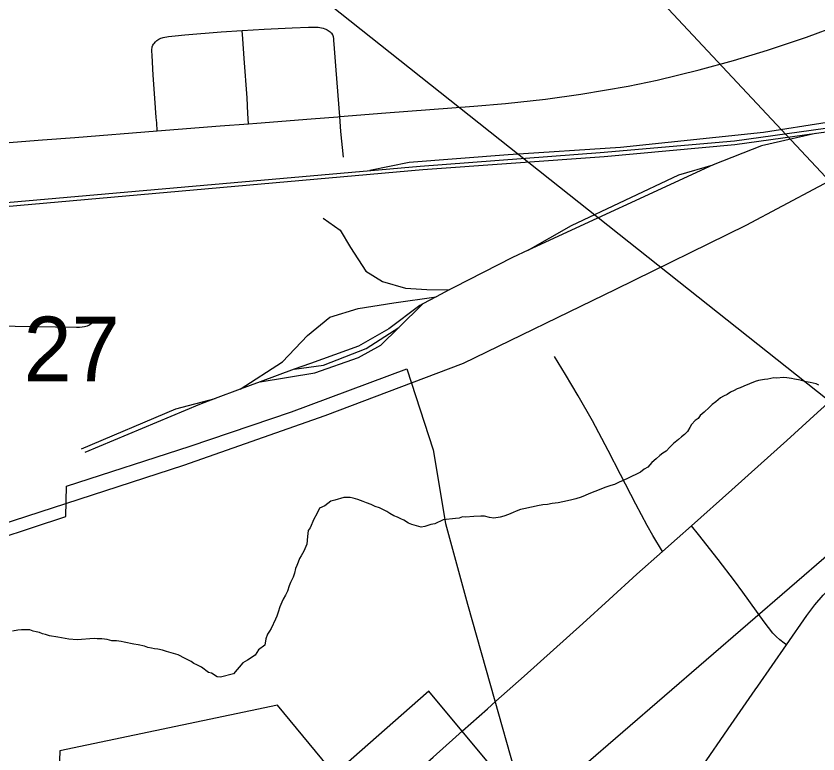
# Model space of a CAD drawing. Extents: x 0 to 34, y 0 to 22.
# Drawn here: x 4.887 to 5.405, y 17.65 to 18.127 of the extents above; entities that cross this region are included whole.
import ezdxf

# ---------------------------------------------------------------- set-up
doc = ezdxf.new("R2010")
doc.units = 0
for name, color, linetype in [('Default', 7, 'Continuous'), ('GM_X_City_Street', 7, 'Continuous'), ('GM_X_County_Road', 7, 'Continuous'), ('GM_X_Minor_River', 7, 'Continuous'), ('GM_X_Rail_Line', 7, 'Continuous'), ('GM_X_Section_Text', 7, 'Continuous'), ('GM_X_State_Route', 7, 'Continuous'), ('SH_Text', 7, 'Continuous')]:
    doc.layers.add(name, color=color, linetype=linetype)

msp = doc.modelspace()

# ---------------------------------------------------------------- linework, layer by layer
at = {"layer": 'Default'}
for points in [[(4.29581, 17.61729), (4.4133, 17.65564), (4.41266, 17.63545), (4.52142, 17.67154), (4.6008, 17.69786), (4.68152, 17.72464), (4.788, 17.76059), (4.91881, 17.80385), (4.91919, 17.82345), (4.99912, 17.84925), (5.06464, 17.8714), (5.13933, 17.89918), (5.15621, 17.84687), (5.16426, 17.7993), (5.17835, 17.74707), (5.19619, 17.68449), (5.20849, 17.64104)], [(5.19842, 17.63675), (5.15355, 17.69077), (5.09248, 17.63721), (5.05555, 17.68167), (4.91492, 17.65219), (4.91134, 17.55474)]]:
    msp.add_lwpolyline(points, dxfattribs=at)
at = {"layer": 'GM_X_City_Street'}
for points in [[(4.97539, 18.10917), (4.97576, 18.10972), (4.97662, 18.1107), (4.97712, 18.11115), (4.97765, 18.1116), (4.97826, 18.11206), (4.97889, 18.11243), (4.9802, 18.11305), (4.98094, 18.11329), (4.98176, 18.1135), (4.98505, 18.11408), (4.98941, 18.11466), (4.99578, 18.11524), (5.01911, 18.11711), (5.03282, 18.11798), (5.04706, 18.11888), (5.06498, 18.11987), (5.07568, 18.1202), (5.08028, 18.12029), (5.08188, 18.12017), (5.08303, 18.12001), (5.08407, 18.1198), (5.08522, 18.11947), (5.08628, 18.1191), (5.08694, 18.11881), (5.08764, 18.11848), (5.08838, 18.11807), (5.089, 18.11771), (5.08961, 18.11725), (5.09019, 18.11676), (5.09069, 18.11623)], [(5.03693, 18.05774), (5.03652, 18.06447), (5.0359, 18.07452), (5.03408, 18.09987), (5.03319, 18.11267), (5.03282, 18.11798)], [(5.09837, 18.0361), (5.09656, 18.05278), (5.09582, 18.06236), (5.09352, 18.09245), (5.0923, 18.10919), (5.09209, 18.11154), (5.09193, 18.11298), (5.09176, 18.114), (5.09135, 18.1152), (5.09069, 18.11623)], [(4.97786, 18.0532), (4.97748, 18.05839), (4.97723, 18.06184), (4.97626, 18.0743), (4.97512, 18.08911), (4.97445, 18.1019), (4.97437, 18.10482), (4.97441, 18.10589), (4.97449, 18.10675), (4.97465, 18.10749), (4.97506, 18.1086), (4.97539, 18.10917)], [(4.87251, 17.92717), (4.91196, 17.92647), (4.92562, 17.92617), (4.92766, 17.92622), (4.92935, 17.92639), (4.93071, 17.9266), (4.93177, 17.92688), (4.93264, 17.92717), (4.9335, 17.92753), (4.93428, 17.92795), (4.9351, 17.92848), (4.9358, 17.92903), (4.93651, 17.9297), (4.93814, 17.93157)], [(5.30447, 17.78105), (5.2983, 17.79155), (5.29453, 17.79796), (5.28732, 17.81168), (5.27737, 17.83098), (5.26944, 17.84645), (5.2592, 17.86559), (5.25009, 17.8818), (5.24175, 17.8956), (5.23461, 17.90724)], [(5.3847, 17.72074), (5.38316, 17.72188), (5.38032, 17.72396), (5.37805, 17.72606), (5.37591, 17.72842), (5.37031, 17.73556), (5.35653, 17.75484), (5.35109, 17.76223), (5.34054, 17.77602), (5.32777, 17.7921), (5.32326, 17.79778)]]:
    msp.add_lwpolyline(points, dxfattribs=at)
at = {"layer": 'GM_X_County_Road'}
for points in [[(5.09582, 18.06236), (5.12563, 18.0648), (5.18258, 18.06906), (5.203, 18.07089), (5.22892, 18.07371), (5.25167, 18.07685), (5.28228, 18.08205), (5.3011, 18.08596), (5.32826, 18.09252), (5.35042, 18.0986), (5.37239, 18.1053), (5.39771, 18.1138), (5.41865, 18.1216), (5.42662, 18.12496)], [(5.03693, 18.05774), (5.04215, 18.05815), (5.07737, 18.06097), (5.09466, 18.06226), (5.09582, 18.06236)], [(4.97786, 18.0532), (5.01863, 18.05635), (5.03693, 18.05774)], [(4.87373, 18.04492), (4.90358, 18.04729), (4.92449, 18.04891), (4.97786, 18.0532)], [(5.32326, 17.79778), (5.34929, 17.82095), (5.36829, 17.83793), (5.38483, 17.853), (5.40466, 17.87091), (5.4176, 17.88255), (5.43056, 17.89417), (5.44588, 17.90782), (5.45927, 17.91988), (5.48745, 17.9452), (5.49668, 17.95337)], [(5.30447, 17.78105), (5.314, 17.78954), (5.32326, 17.79778)], [(5.19687, 17.68442), (5.21513, 17.70052), (5.25305, 17.73458), (5.2701, 17.75), (5.28799, 17.76638), (5.30447, 17.78105)], [(5.17531, 17.66512), (5.19139, 17.67947), (5.19687, 17.68442)], [(5.02881, 17.53513), (5.06817, 17.56945), (5.08248, 17.58233), (5.10145, 17.59932), (5.14539, 17.63872), (5.15619, 17.64806), (5.17093, 17.66138), (5.17531, 17.66512)]]:
    msp.add_lwpolyline(points, dxfattribs=at)
at = {"layer": 'GM_X_Minor_River'}
for points in [[(3.74301, 16.33754), (5.62913, 17.96708)], [(5.40571, 17.8888), (5.40383, 17.8896), (5.40194, 17.89003), (5.40005, 17.89046), (5.3974, 17.89091), (5.39439, 17.89174), (5.3925, 17.89217), (5.38985, 17.89262), (5.38796, 17.89305), (5.38493, 17.8935), (5.38266, 17.89356), (5.37847, 17.89328), (5.37657, 17.89333), (5.37275, 17.89267), (5.37047, 17.89235), (5.36665, 17.89169), (5.36436, 17.89098), (5.35707, 17.88813), (5.35476, 17.88705), (5.35285, 17.88634), (5.35092, 17.88525), (5.34861, 17.88416), (5.3463, 17.88271), (5.34399, 17.88162), (5.34206, 17.88053), (5.33896, 17.87795), (5.33664, 17.87611), (5.33469, 17.87426), (5.33158, 17.8713), (5.32886, 17.86909), (5.32768, 17.86722), (5.32574, 17.86575), (5.3234, 17.86316), (5.32221, 17.86128), (5.32062, 17.85867), (5.31868, 17.85682), (5.31674, 17.85535), (5.3148, 17.8535), (5.31169, 17.85092), (5.30936, 17.8487), (5.30701, 17.8461), (5.3047, 17.84464), (5.30276, 17.84317), (5.30043, 17.84095), (5.29771, 17.83874), (5.29498, 17.83577), (5.29266, 17.83431), (5.29034, 17.83247), (5.28726, 17.83102), (5.28496, 17.82994), (5.28226, 17.82849), (5.27919, 17.82705), (5.2765, 17.82598), (5.27343, 17.82454), (5.27113, 17.82384), (5.26921, 17.82313), (5.2673, 17.82241), (5.26461, 17.82134), (5.25694, 17.8185), (5.25464, 17.81742), (5.25195, 17.81635), (5.2485, 17.81529), (5.24583, 17.8146), (5.24315, 17.81391), (5.2401, 17.81323), (5.23704, 17.81255), (5.23323, 17.81226), (5.23018, 17.81158), (5.22713, 17.81128), (5.2237, 17.8106), (5.22102, 17.80991), (5.21873, 17.80959), (5.21606, 17.8089), (5.21262, 17.80823), (5.20993, 17.80716), (5.20802, 17.80645), (5.20494, 17.805), (5.20188, 17.80394), (5.19958, 17.80324), (5.19539, 17.80259), (5.19274, 17.80303), (5.18934, 17.80388), (5.18706, 17.80394), (5.1825, 17.80367), (5.17717, 17.80343), (5.17528, 17.80348), (5.17298, 17.80277), (5.17069, 17.80245), (5.16269, 17.80152), (5.15731, 17.79899), (5.15464, 17.79868), (5.15081, 17.79726)], [(5.15081, 17.79726), (5.14852, 17.79694), (5.14249, 17.79861), (5.14023, 17.79942), (5.13724, 17.8014), (5.13536, 17.80221), (5.13311, 17.8034), (5.13085, 17.80422), (5.12823, 17.80581), (5.12636, 17.80699), (5.12448, 17.8078), (5.12148, 17.80939), (5.11884, 17.81022), (5.11622, 17.81143), (5.11321, 17.81264), (5.11095, 17.81346), (5.10756, 17.81469), (5.10454, 17.81552), (5.10265, 17.81595), (5.10076, 17.816), (5.09848, 17.81606), (5.09274, 17.8143), (5.09006, 17.81361), (5.08619, 17.81067), (5.08273, 17.80924), (5.08112, 17.80548), (5.07914, 17.80211), (5.07672, 17.79648), (5.07553, 17.79461), (5.07506, 17.79082), (5.07455, 17.78589), (5.07254, 17.78139), (5.07095, 17.77839), (5.06976, 17.77652), (5.06894, 17.77426), (5.06813, 17.77201), (5.06732, 17.77013), (5.06649, 17.76711), (5.06566, 17.76447), (5.06406, 17.76109), (5.06324, 17.75884), (5.06202, 17.75545), (5.06081, 17.75282), (5.05922, 17.7502), (5.05842, 17.74832), (5.0572, 17.74531), (5.05598, 17.74193), (5.05515, 17.73929), (5.05435, 17.73741), (5.05154, 17.7314), (5.05035, 17.72953), (5.04916, 17.72766), (5.04795, 17.72466), (5.04746, 17.72049), (5.04321, 17.71756), (5.04123, 17.71419), (5.03621, 17.7109), (5.03313, 17.70908), (5.02725, 17.70201), (5.01884, 17.69995), (5.01656, 17.7), (5.01282, 17.70238), (5.01094, 17.70281), (5.00647, 17.70634), (5.00347, 17.70793), (5.00159, 17.70874), (4.99972, 17.70993), (4.99597, 17.71192), (4.99147, 17.71431), (4.98694, 17.71557), (4.98393, 17.7164), (4.98129, 17.71723), (4.97827, 17.71807), (4.97599, 17.71812), (4.9741, 17.71855), (4.97184, 17.71899), (4.96958, 17.71981), (4.96542, 17.72067), (4.96277, 17.72112), (4.9605, 17.72155), (4.95861, 17.72198), (4.95635, 17.72242), (4.95446, 17.72285), (4.95143, 17.7233), (4.94839, 17.72338), (4.94538, 17.72422), (4.94197, 17.72468), (4.93893, 17.72476), (4.93703, 17.72481), (4.926, 17.72395), (4.92069, 17.72446), (4.91351, 17.72578), (4.90821, 17.72668), (4.90557, 17.7275), (4.90368, 17.72793), (4.90181, 17.72874), (4.89954, 17.72918), (4.89765, 17.7296), (4.89539, 17.73042), (4.89311, 17.73048), (4.89007, 17.73056)], [(4.89007, 17.73056), (4.88779, 17.73023), (4.88435, 17.72956)]]:
    msp.add_lwpolyline(points, dxfattribs=at)
at = {"layer": 'GM_X_Rail_Line'}
for p, q in [((5.33721, 18.03123), (5.21771, 17.97593)), ((5.16663, 17.95036), (5.15828, 17.94591)), ((5.13415, 17.92603), (5.14961, 17.9413)), ((5.15828, 17.94591), (5.14961, 17.9413)), ((5.06646, 17.89895), (5.04442, 17.8908)), ((5.04442, 17.8908), (5.03142, 17.886)), ((5.03142, 17.886), (5.01533, 17.88005))]:
    msp.add_line(p, q, dxfattribs=at)
for points in [[(5.97495, 18.45163), (5.79508, 18.29756), (5.69294, 18.21372), (5.64547, 18.17693), (5.58053, 18.12987), (5.54806, 18.1085), (5.51148, 18.08507), (5.49011, 18.07644), (5.46483, 18.06966), (5.41099, 18.05856), (5.36989, 18.05198), (5.27741, 18.04232), (5.20466, 18.0376), (5.14075, 18.03267), (5.11521, 18.02753)], [(3.18695, 17.8856), (3.2694, 17.88298), (3.3466, 17.88821), (3.45467, 17.89411), (3.58303, 17.90459), (3.67737, 17.91311), (4.18614, 17.95435), (4.79172, 17.99896), (5.14774, 18.0304), (5.26426, 18.03924), (5.35106, 18.04678), (5.42697, 18.05726)], [(3.1869, 17.88311), (3.26945, 17.88049), (3.34675, 17.88573), (3.45484, 17.89163), (3.58324, 17.90212), (3.67758, 17.91064), (4.1812, 17.95168), (4.79192, 17.99648), (5.14959, 18.02814), (5.26693, 18.03657), (5.35138, 18.04432), (5.42737, 18.05481)], [(5.40346, 18.05151), (5.36866, 18.04356), (5.33721, 18.03123)], [(2.38289, 16.983), (4.2841, 17.60614), (4.99507, 17.83701), (5.08648, 17.869), (5.17577, 17.90296), (5.27433, 17.95087), (5.35859, 17.99218), (5.42907, 18.02958)], [(5.21771, 17.97593), (5.24576, 17.99198), (5.31502, 18.02465), (5.33721, 18.03123)], [(5.08506, 17.9967), (5.09616, 17.98889), (5.10273, 17.9778), (5.1128, 17.96238), (5.12349, 17.95581), (5.13828, 17.95149), (5.15226, 17.95046), (5.16663, 17.95036)], [(5.21771, 17.97593), (5.20754, 17.97122), (5.16952, 17.9519), (5.16663, 17.95036)], [(5.03142, 17.886), (5.05875, 17.90381), (5.07499, 17.92087), (5.08937, 17.93258), (5.10766, 17.93834), (5.13089, 17.94183), (5.15828, 17.94591)], [(5.14961, 17.9413), (5.14753, 17.94019), (5.1276, 17.92519), (5.10787, 17.91388), (5.07684, 17.90279), (5.06646, 17.89895)], [(5.04442, 17.8908), (5.07972, 17.89662), (5.10787, 17.90649), (5.12246, 17.9145), (5.13415, 17.92603)], [(5.06646, 17.89895), (5.08526, 17.90155), (5.11301, 17.91244), (5.13415, 17.92603)], [(4.92887, 17.84751), (4.98991, 17.8734), (5.01533, 17.88005)], [(5.01533, 17.88005), (5.00512, 17.87628), (4.93093, 17.84524)]]:
    msp.add_lwpolyline(points, dxfattribs=at)
at = {"layer": 'GM_X_State_Route'}
for points in [[(5.36628, 17.69414), (5.3847, 17.72074), (5.39784, 17.73971), (5.4031, 17.74669), (5.40834, 17.75291), (5.41265, 17.75747), (5.41811, 17.76263), (5.42484, 17.76822), (5.43619, 17.77695), (5.46455, 17.79819), (5.48886, 17.81652), (5.50374, 17.82775), (5.52342, 17.84294), (5.5384, 17.85407), (5.56038, 17.87036), (5.58575, 17.88936), (5.59145, 17.89367)], [(5.15088, 17.3809), (5.17503, 17.41639), (5.18376, 17.42923), (5.20878, 17.46568), (5.21201, 17.47039), (5.23382, 17.50213), (5.25471, 17.53248), (5.26413, 17.54582), (5.27159, 17.55663), (5.30351, 17.60343), (5.3285, 17.63948), (5.34898, 17.66916), (5.36455, 17.69165), (5.36628, 17.69414)]]:
    msp.add_lwpolyline(points, dxfattribs=at)
at = {"layer": 'SH_Text'}
msp.add_line((5.08107, 18.14149), (5.93202, 17.46601), dxfattribs=at)
msp.add_lwpolyline([(5.93202, 17.46601), (5.20653, 18.24084)], dxfattribs=at)

# ---------------------------------------------------------------- texts
at = {"layer": 'GM_X_Section_Text'}
msp.add_text('27', height=0.041856, rotation=0, dxfattribs=at).set_placement((4.89139, 17.89115))

doc.saveas('drawing.dxf')
